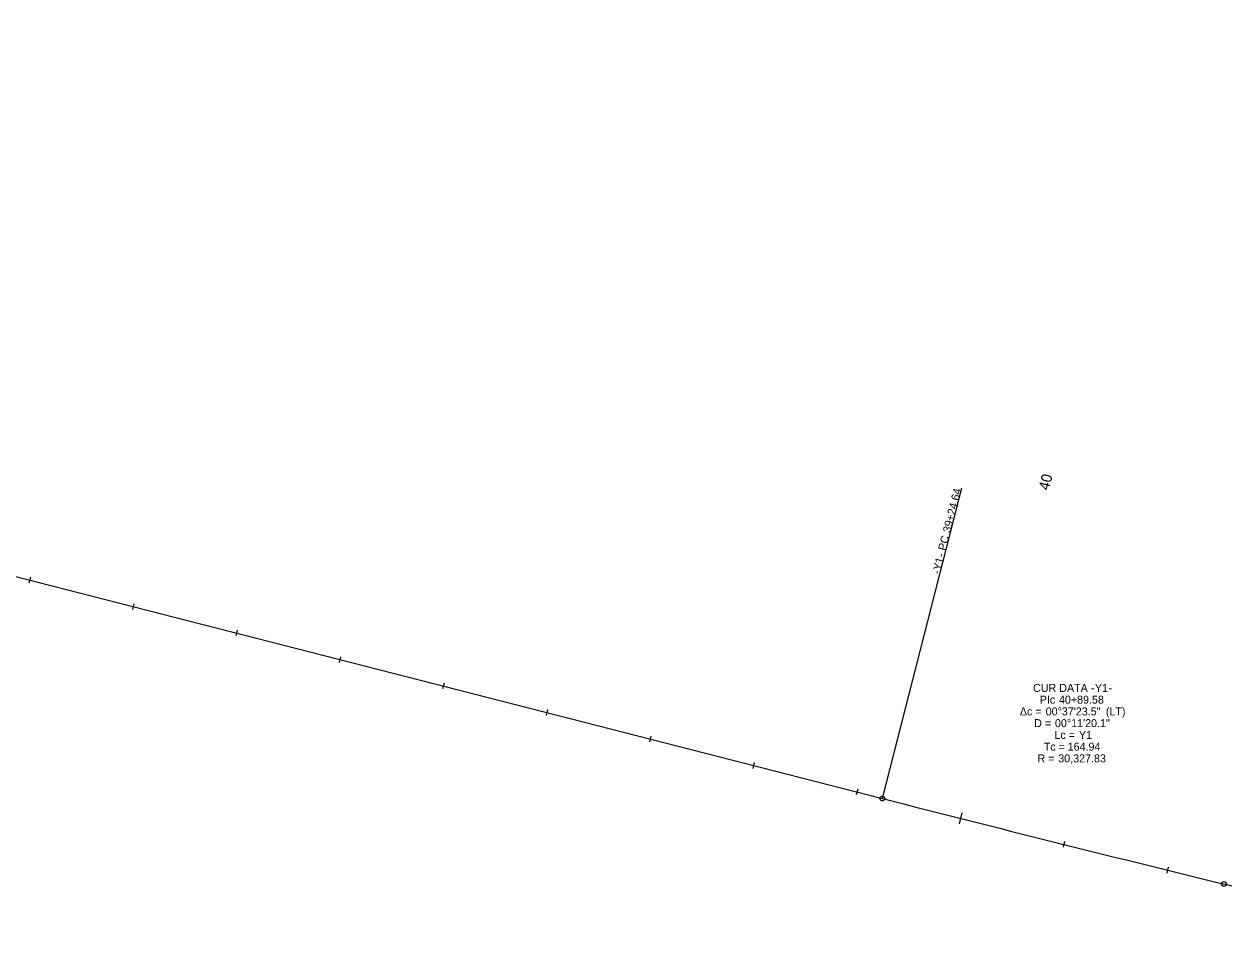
# Model space of a CAD drawing. Extents: x 1182527 to 1186622, y 573661 to 574910.
# Drawn here: x 1184558 to 1185682, y 573716 to 574588 of the extents above; entities that cross this region are included whole.
import ezdxf

# ---------------------------------------------------------------- set-up
doc = ezdxf.new("R2010")
doc.units = 0
for name, color, linetype in [('Default', 7, 'Continuous'), ('E_NCDOT_Vertical_Profile_Ground_Line', 7, 'Continuous'), ('P_HYD_Contour_Major', 7, 'Continuous'), ('P_HYD_Contour_Minor', 7, 'Continuous'), ('P_HYD_TL_Ditch_Mid', 7, 'Continuous'), ('P_HYD_TL_Slope_Stake_Fill', 7, 'Continuous'), ('Scratch_Level_0', 7, 'Continuous')]:
    doc.layers.add(name, color=color, linetype=linetype)

msp = doc.modelspace()

# ---------------------------------------------------------------- linework, layer by layer
at = {"layer": 'Default'}
for centre, radius, start, end in [((1192883.6, 603243.2), 30327.8, 255.64052, 256.26372), ((1186442.7, 576894.2), 3203, 256.2637, 262.8215)]:
    msp.add_arc(centre, radius, start, end, dxfattribs=at)
at = {"layer": 'P_HYD_Contour_Major'}
msp.add_line((1185362.1, 573862.9), (1185436.5, 574153.5), dxfattribs=at)
for centre in [(1185362.1, 573862.9), (1185682.2, 573782.8)]:
    msp.add_circle(centre, 2.25, dxfattribs=at)
at = {"layer": 'P_HYD_TL_Ditch_Mid'}
for p, q in [((1184564, 574070.1), (1184562.6, 574064.7)), ((1184660.8, 574045.3), (1184659.5, 574039.9)), ((1184757.7, 574020.5), (1184756.3, 574015.1)), ((1184854.6, 573995.7), (1184853.2, 573990.3)), ((1184951.5, 573970.9), (1184950.1, 573965.5)), ((1185048.3, 573946.1), (1185047, 573940.7)), ((1185145.2, 573921.3), (1185143.8, 573915.9)), ((1185242.1, 573896.5), (1185240.7, 573891.1)), ((1185339, 573871.7), (1185337.6, 573866.3)), ((1185532.8, 573822.6), (1185531.5, 573817.2)), ((1185629.9, 573798.5), (1185628.6, 573793.1))]:
    msp.add_line(p, q, dxfattribs=at)
at = {"layer": 'P_HYD_TL_Slope_Stake_Fill'}
msp.add_line((1185436.5, 573849.5), (1185433.9, 573839.2), dxfattribs=at)
at = {"layer": 'Scratch_Level_0'}
msp.add_line((1182528.9, 574588.2), (1185362.1, 573862.9), dxfattribs=at)
msp.add_arc((1192883.6, 603243.2), 30327.8, 255.64052, 256.26372, dxfattribs=at)

# ---------------------------------------------------------------- texts
at = {"layer": 'E_NCDOT_Vertical_Profile_Ground_Line'}
for s, p in [('CUR DATA -', (1185503.3, 573962.7)), ('Y1', (1185561.2, 573962.7)), ('PIc ', (1185509.5, 573951.7)), ('40+89.58', (1185527.5, 573951.7)), ('-', (1185574, 573962.7)), ('Δc = ', (1185490.9, 573940.7)), ('00°37\'23.5"', (1185515.1, 573940.7)), (' (LT)', (1185568.7, 573940.7)), ('D = ', (1185504.3, 573929.7)), ('00°11\'20.1"', (1185523.8, 573929.7)), ('Lc = ', (1185523.3, 573918.7)), ('Y1', (1185546.3, 573918.7)), ('Tc = ', (1185513.3, 573907.7)), ('164.94', (1185535.7, 573907.7)), ('R = ', (1185507.4, 573896.7)), ('30,327.83', (1185526.9, 573896.7))]:
    msp.add_text(s, height=7.5, dxfattribs=at).set_placement(p)
at = {"layer": 'P_HYD_Contour_Major'}
for s, p in [('39+24.64', (1185425.8, 574111.4)), ('PC', (1185421.4, 574094.5)), ('- ', (1185419.8, 574088.3)), ('Y1', (1185416.7, 574075.9)), ('-', (1185415.8, 574072.5))]:
    msp.add_text(s, height=7.5, rotation=75.6405, dxfattribs=at).set_placement(p)
at = {"layer": 'P_HYD_Contour_Minor'}
msp.add_text('40', height=10, rotation=75.7829, dxfattribs=at).set_placement((1185518, 574150.9))

doc.saveas('drawing.dxf')
